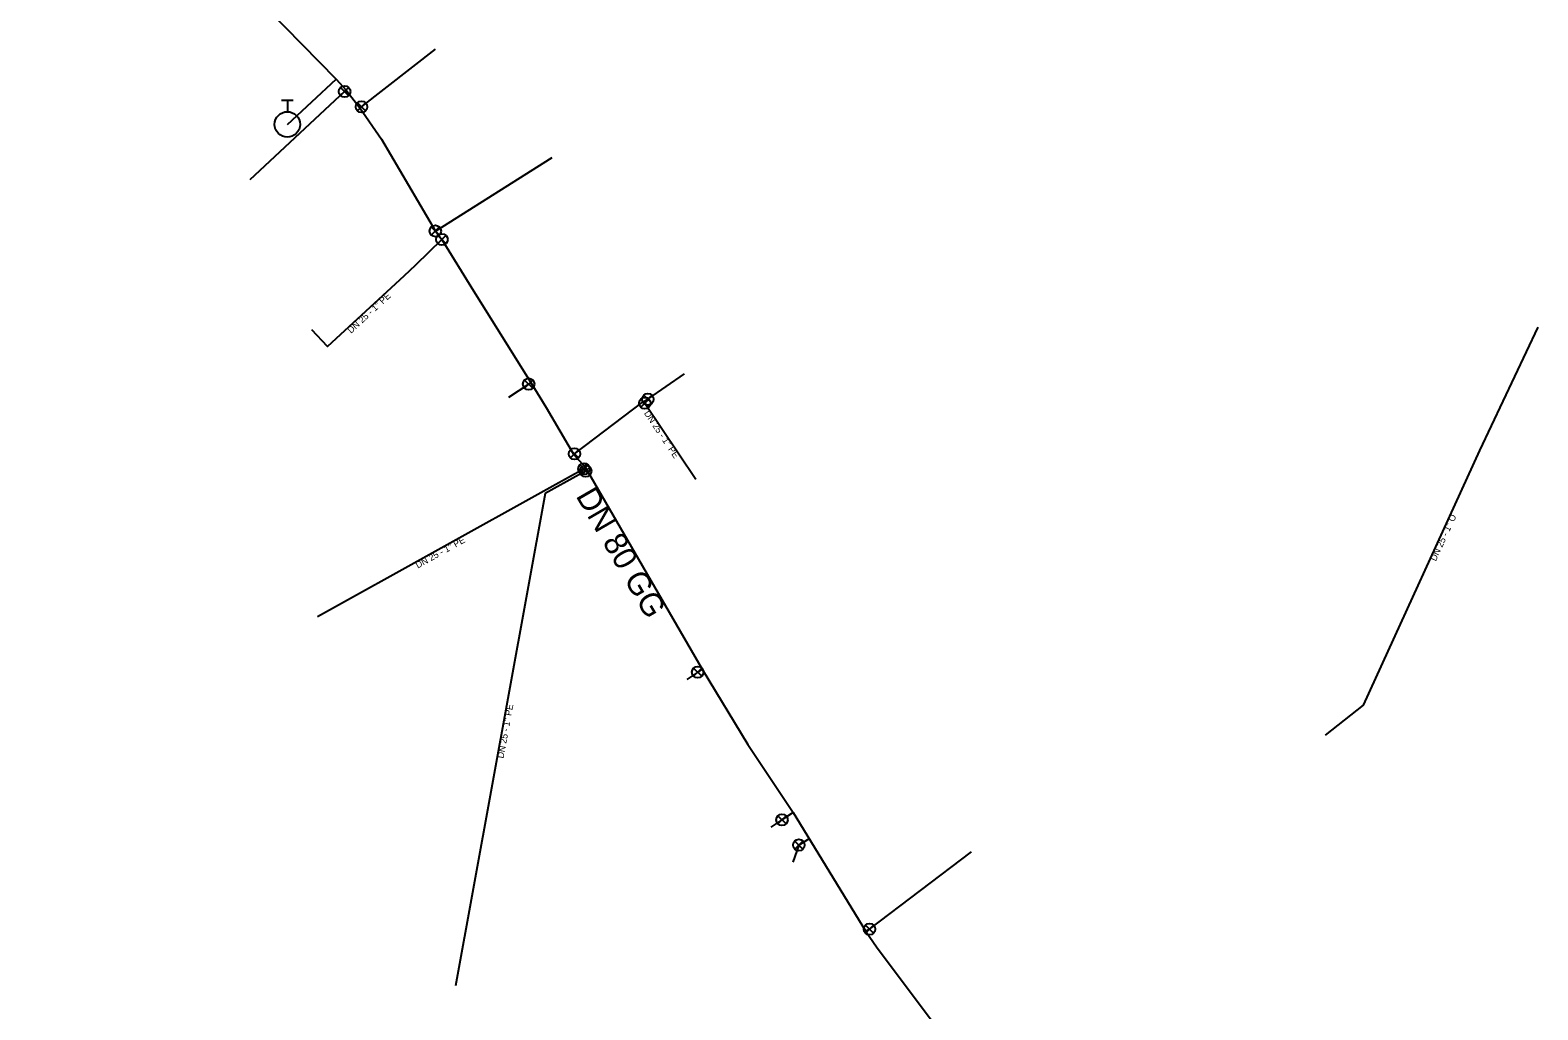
# Model space of a CAD drawing. Extents: x -484784 to -484458, y -1128042 to -1127614.
# Drawn here: x -484646.3 to -484541.5, y -1127873.7 to -1127805.6 of the extents above; entities that cross this region are included whole.
import ezdxf

# ---------------------------------------------------------------- set-up
doc = ezdxf.new("R2010")
doc.units = 0
for name, color, linetype in [('_hydrantova_odbocka_', 7, 'Continuous'), ('_pripojka_prevzato_z_dokumentace_', 7, 'Continuous'), ('_pripojka_priblizne_', 7, 'Continuous'), ('_voda_smvak_prevzato_z_dokumentace_', 7, 'Continuous'), ('Default', 7, 'Continuous'), ('MoLevel 28', 7, 'Continuous'), ('MoLevel 32', 7, 'Continuous'), ('MoLevel 46', 7, 'Continuous'), ('MoLevel 53', 7, 'Continuous'), ('MoLevel 55', 7, 'Continuous')]:
    doc.layers.add(name, color=color, linetype=linetype)

# ---------------------------------------------------------------- blocks, each defined once
blk = doc.blocks.new('_uzaver_pripojka_')
at = {"layer": 'Default'}
for p, q in [((-0.000035, -0.000035), (0.000035, 0.000035)), ((0.000035, -0.000035), (-0.000035, 0.000035))]:
    blk.add_line(p, q, dxfattribs=at)
for radius in [0.00005, 0.0000025]:
    blk.add_circle((0, 0), radius, dxfattribs=at)
blk = doc.blocks.new('_hydrant_voda_')
at = {"layer": 'Default'}
for p, q in [((-0.0000225, 0.000095), (0.0000225, 0.000095)), ((0, 0.000095), (0, 0.00005))]:
    blk.add_line(p, q, dxfattribs=at)
blk.add_circle((0, 0), 0.00005, dxfattribs=at)

msp = doc.modelspace()

# ---------------------------------------------------------------- linework, layer by layer
at = {"layer": '_hydrantova_odbocka_'}
msp.add_line((-484628.4, -1127812.12), (-484625, -1127808.97), dxfattribs=at)
at = {"layer": '_pripojka_prevzato_z_dokumentace_'}
for p, q in [((-484618.11, -1127819.53), (-484609.99, -1127814.43)), ((-484617.65, -1127820.12), (-484619.49, -1127821.9)), ((-484609.95, -1127837.27), (-484626.31, -1127846.36))]:
    msp.add_line(p, q, dxfattribs=at)
for points in [[(-484623.36, -1127810.97), (-484623.24, -1127810.9), (-484618.09, -1127806.88)], [(-484624.3, -1127809.74), (-484624.42, -1127809.83), (-484631.01, -1127815.97)], [(-484619.49, -1127821.9), (-484620.3, -1127822.67), (-484625.6, -1127827.56), (-484626.7, -1127826.41)], [(-484608.51, -1127835.04), (-484608.44, -1127835.02), (-484603.64, -1127831.39), (-484603.34, -1127831.23), (-484600.78, -1127829.45)], [(-484611.48, -1127830.07), (-484611.62, -1127830.17), (-484613.02, -1127831.1)], [(-484603.64, -1127831.39), (-484603.54, -1127831.5), (-484600.01, -1127836.78)], [(-484607.7, -1127835.95), (-484607.77, -1127836.06), (-484609.95, -1127837.27)], [(-484599.55, -1127849.98), (-484599.87, -1127850.2), (-484600.63, -1127850.7)], [(-484593.24, -1127859.96), (-484594.01, -1127860.47), (-484594.78, -1127860.98)], [(-484588.21, -1127868.19), (-484587.92, -1127868.07), (-484580.83, -1127862.7)]]:
    msp.add_lwpolyline(points, dxfattribs=at)
at = {"layer": '_pripojka_priblizne_'}
for points in [[(-484541.46, -1127826.21), (-484545.52, -1127834.8), (-484553.61, -1127852.5), (-484556.25, -1127854.57)], [(-484607.55, -1127836.17), (-484607.66, -1127836.22), (-484609.84, -1127837.44)], [(-484609.84, -1127837.44), (-484610.47, -1127837.79), (-484616.72, -1127872)], [(-484592.13, -1127861.78), (-484592.84, -1127862.22), (-484593.25, -1127863.41)]]:
    msp.add_lwpolyline(points, dxfattribs=at)
at = {"layer": '_voda_smvak_prevzato_z_dokumentace_'}
msp.add_lwpolyline([(-484648.49, -1127785.58), (-484632.11, -1127801.7), (-484625, -1127808.97), (-484624.3, -1127809.74), (-484623.36, -1127810.97), (-484621.85, -1127813.14), (-484618.11, -1127819.53), (-484617.65, -1127820.12), (-484615.46, -1127823.69), (-484611.48, -1127830.07), (-484610.4, -1127831.79), (-484608.51, -1127835.04), (-484607.7, -1127835.95), (-484607.55, -1127836.17), (-484599.55, -1127849.98), (-484596.39, -1127855.24), (-484593.24, -1127859.96), (-484588.21, -1127868.19), (-484587.4, -1127869.37), (-484583.47, -1127874.59)], dxfattribs=at)

# ---------------------------------------------------------------- block references
at = {"layer": 'MoLevel 28', "xscale": 17636.68430335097, "yscale": 17636.68430335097}
msp.add_blockref('_hydrant_voda_', (-484628.4, -1127812.12), dxfattribs=at)
at = {"layer": 'MoLevel 53', "xscale": 7999.999999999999, "yscale": 7999.999999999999}
for p in [(-484624.42, -1127809.83), (-484623.24, -1127810.9), (-484618.11, -1127819.53), (-484617.65, -1127820.12), (-484611.62, -1127830.17), (-484603.54, -1127831.5), (-484603.34, -1127831.23), (-484608.44, -1127835.02), (-484607.77, -1127836.06), (-484607.66, -1127836.22), (-484599.87, -1127850.2), (-484594.01, -1127860.47), (-484592.84, -1127862.22), (-484587.92, -1127868.07)]:
    msp.add_blockref('_uzaver_pripojka_', p, dxfattribs=at)

# ---------------------------------------------------------------- texts
at = {"layer": 'MoLevel 32'}
for s, rotation, p in [("DN 25 - 1'' O", 65.4362, (-484548.55, -1127842.52)), ("DN 25 - 1'' PE", 79.6424, (-484613.37, -1127856.22))]:
    msp.add_text(s, height=0.455, rotation=rotation, dxfattribs=at).set_placement(p)
at = {"layer": 'MoLevel 46'}
msp.add_text('DN 80 GG', height=1.605, rotation=300.0709, dxfattribs=at).set_placement((-484608.38, -1127837.94))
at = {"layer": 'MoLevel 55'}
for rotation, p in [(42.6622, (-484623.97, -1127826.68)), (303.7901, (-484603.62, -1127832.2)), (29.0423, (-484619.33, -1127843))]:
    msp.add_text("DN 25 - 1'' PE", height=0.455, rotation=rotation, dxfattribs=at).set_placement(p)

doc.saveas('drawing.dxf')
